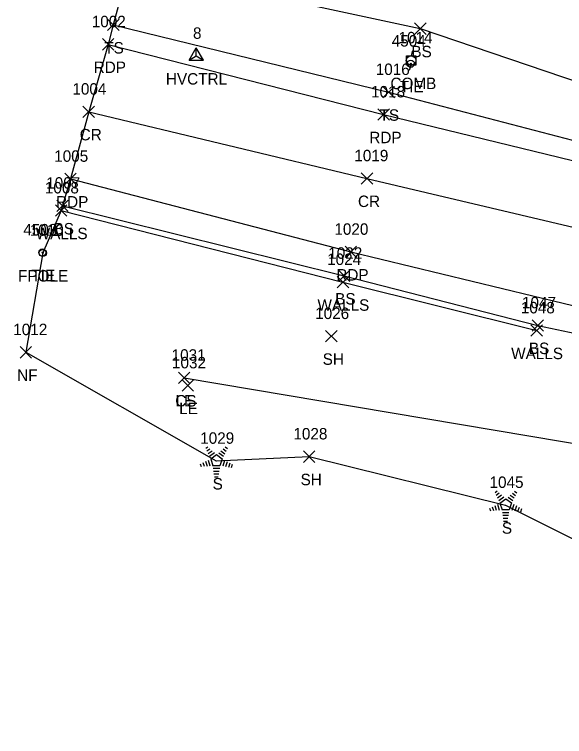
# Model space of a CAD drawing. Extents: x 1509053 to 1511576, y 400838 to 402572.
# Drawn here: x 1509053.4 to 1509149.6, y 402041.6 to 402167.8 of the extents above; entities that cross this region are included whole.
import ezdxf

# ---------------------------------------------------------------- set-up
doc = ezdxf.new("R2010")
doc.units = 0
for name, color, linetype in [('C_A', 7, 'Continuous'), ('C_I', 7, 'Continuous'), ('CBP', 7, 'Continuous'), ('CPSM', 7, 'Continuous'), ('L_A', 7, 'Continuous'), ('L_I', 7, 'Continuous'), ('L_TIC', 7, 'Continuous'), ('LELB', 7, 'Continuous'), ('LFP', 7, 'Continuous'), ('LSOGP', 7, 'Continuous'), ('LTC', 7, 'Continuous'), ('LWS', 7, 'Continuous'), ('P_A', 7, 'Continuous'), ('P_I', 7, 'Continuous'), ('P_TIC', 7, 'Continuous'), ('PET', 7, 'Continuous'), ('PRC', 7, 'Continuous'), ('U_A', 7, 'Continuous'), ('U_I', 7, 'Continuous'), ('UP', 7, 'Continuous')]:
    doc.layers.add(name, color=color, linetype=linetype)

msp = doc.modelspace()

# ---------------------------------------------------------------- linework, layer by layer
at = {"layer": 'CBP'}
for centre, radius in [((1509122.7, 402159.23), 0.625), ((1509122.7, 402159.23), 0.0833), ((1509058.25, 402126.22), 0.625), ((1509058.25, 402126.22), 0.0833)]:
    msp.add_circle(centre, radius, dxfattribs=at)
at = {"layer": 'CPSM'}
for p, q in [((1509083.92, 402159.86), (1509085.17, 402162.03)), ((1509086.42, 402159.86), (1509085.17, 402162.03)), ((1509085.17, 402160.58), (1509085.17, 402162.03)), ((1509083.92, 402159.86), (1509085.17, 402160.58)), ((1509083.92, 402159.86), (1509086.42, 402159.86)), ((1509085.17, 402160.58), (1509085.17, 402160.58)), ((1509085.17, 402160.58), (1509086.42, 402159.86))]:
    msp.add_line(p, q, dxfattribs=at)
at = {"layer": 'L_TIC'}
for points in [[(1509069.66, 402165.01), (1509071.66, 402167.01)], [(1509071.66, 402165.01), (1509069.66, 402167.01)], [(1509123.36, 402164.36), (1509125.36, 402166.36)], [(1509125.36, 402164.36), (1509123.36, 402166.36)], [(1509117.82, 402153.26), (1509119.82, 402155.26)], [(1509119.82, 402153.26), (1509117.82, 402155.26)], [(1509060.54, 402132.56), (1509062.54, 402134.56)], [(1509062.54, 402132.56), (1509060.54, 402134.56)], [(1509060.77, 402133.39), (1509062.77, 402135.39)], [(1509062.77, 402133.39), (1509060.77, 402135.39)], [(1509110.03, 402121.14), (1509112.03, 402123.14)], [(1509112.03, 402121.14), (1509110.03, 402123.14)], [(1509109.83, 402120.05), (1509111.83, 402122.05)], [(1509111.83, 402120.05), (1509109.83, 402122.05)], [(1509143.92, 402112.48), (1509145.92, 402114.48)], [(1509145.92, 402112.48), (1509143.92, 402114.48)], [(1509143.72, 402111.59), (1509145.72, 402113.59)], [(1509145.72, 402111.59), (1509143.72, 402113.59)], [(1509107.79, 402110.6), (1509109.79, 402112.6)], [(1509109.79, 402110.6), (1509107.79, 402112.6)], [(1509054.36, 402107.79), (1509056.36, 402109.79)], [(1509056.36, 402107.79), (1509054.36, 402109.79)], [(1509082.06, 402103.32), (1509084.06, 402105.32)], [(1509084.06, 402103.32), (1509082.06, 402105.32)], [(1509082.06, 402103.32), (1509084.06, 402105.32)], [(1509084.06, 402103.32), (1509082.06, 402105.32)], [(1509082.7, 402101.98), (1509084.7, 402103.98)], [(1509084.7, 402101.98), (1509082.7, 402103.98)], [(1509103.93, 402089.55), (1509105.93, 402091.55)], [(1509105.93, 402089.55), (1509103.93, 402091.55)]]:
    msp.add_lwpolyline(points, dxfattribs=at)
at = {"layer": 'LELB'}
for points in [[(1509073.43, 402176.32), (1509124.36, 402165.36), (1509168.15, 402150.53), (1509197.52, 402153.15), (1509206.41, 402183.98), (1509229.57, 402218.52), (1509244.53, 402232.65)], [(1509070.66, 402166.02), (1509118.82, 402154.26), (1509167.06, 402141.7), (1509189.96, 402136.47)], [(1509061.77, 402134.39), (1509111.03, 402122.14), (1509144.92, 402113.48)], [(1509144.92, 402113.48), (1509159.31, 402110.46)], [(1509083.06, 402104.32), (1509155.46, 402092.16)]]:
    msp.add_lwpolyline(points, dxfattribs=at)
at = {"layer": 'LFP'}
for radius in [0.625, 0.0833]:
    msp.add_circle((1509058.33, 402126.15), radius, dxfattribs=at)
at = {"layer": 'LSOGP'}
msp.add_lwpolyline([(1509099.68, 402257.85), (1509084.77, 402216.15), (1509076.57, 402183.15), (1509073.43, 402176.32), (1509070.66, 402166.02), (1509069.74, 402162.61), (1509066.35, 402150.83), (1509063.17, 402139.09), (1509061.77, 402134.39), (1509061.54, 402133.56), (1509058.33, 402126.15), (1509055.36, 402108.79), (1509088.64, 402089.81), (1509104.93, 402090.55), (1509139.24, 402082.08), (1509152.55, 402075.44), (1509177.52, 402071.59), (1509197.64, 402060.42), (1509219.32, 402052.84), (1509231.98, 402043.7), (1509281.69, 402042.53)], dxfattribs=at)
at = {"layer": 'LTC'}
for p, q in [((1509086.84, 402092.01), (1509087.19, 402092.27)), ((1509087.04, 402091.55), (1509087.57, 402091.93)), ((1509087.25, 402091.08), (1509087.96, 402091.59)), ((1509089.49, 402091.56), (1509090.17, 402091.06)), ((1509089.86, 402091.91), (1509090.41, 402091.51)), ((1509090.23, 402092.25), (1509090.65, 402091.95)), ((1509087.46, 402090.62), (1509088.34, 402091.25)), ((1509087.69, 402090.16), (1509088.7, 402090.9)), ((1509088.7, 402090.9), (1509089.7, 402090.17)), ((1509089.12, 402091.21), (1509089.93, 402090.62)), ((1509085.87, 402089.29), (1509086.02, 402088.82)), ((1509086.32, 402089.51), (1509086.53, 402088.86)), ((1509086.78, 402089.73), (1509087.05, 402088.89)), ((1509087.23, 402089.94), (1509087.56, 402088.92)), ((1509087.69, 402090.16), (1509088.08, 402088.97)), ((1509089.7, 402090.17), (1509089.31, 402088.97)), ((1509090.13, 402089.9), (1509089.8, 402088.86)), ((1509090.58, 402089.65), (1509090.29, 402088.76)), ((1509091.02, 402089.4), (1509090.79, 402088.67)), ((1509091.47, 402089.15), (1509091.28, 402088.57)), ((1509089.31, 402088.97), (1509088.08, 402088.97)), ((1509089.27, 402088.47), (1509088.12, 402088.47)), ((1509089.18, 402087.97), (1509088.2, 402087.97)), ((1509089.1, 402087.47), (1509088.27, 402087.47)), ((1509089.02, 402086.97), (1509088.34, 402086.97)), ((1509137.44, 402084.29), (1509137.79, 402084.55)), ((1509137.65, 402083.82), (1509138.18, 402084.21)), ((1509140.47, 402084.18), (1509141.01, 402083.78)), ((1509140.84, 402084.53), (1509141.26, 402084.23)), ((1509137.86, 402083.36), (1509138.56, 402083.87)), ((1509138.07, 402082.89), (1509138.95, 402083.53)), ((1509138.29, 402082.44), (1509139.3, 402083.17)), ((1509139.3, 402083.17), (1509140.3, 402082.45)), ((1509139.72, 402083.49), (1509140.53, 402082.9)), ((1509140.09, 402083.83), (1509140.77, 402083.34)), ((1509136.47, 402081.57), (1509136.62, 402081.1)), ((1509136.93, 402081.79), (1509137.14, 402081.13)), ((1509137.38, 402082), (1509137.65, 402081.17)), ((1509137.84, 402082.22), (1509138.17, 402081.2)), ((1509138.29, 402082.44), (1509138.68, 402081.24)), ((1509140.3, 402082.45), (1509139.91, 402081.24)), ((1509140.74, 402082.18), (1509140.4, 402081.14)), ((1509141.18, 402081.93), (1509140.89, 402081.04)), ((1509141.63, 402081.68), (1509141.39, 402080.95)), ((1509142.07, 402081.43), (1509141.88, 402080.85)), ((1509139.91, 402081.24), (1509138.68, 402081.24)), ((1509139.87, 402080.74), (1509138.73, 402080.74)), ((1509139.79, 402080.24), (1509138.8, 402080.24)), ((1509139.7, 402079.74), (1509138.87, 402079.74)), ((1509139.62, 402079.24), (1509138.94, 402079.24))]:
    msp.add_line(p, q, dxfattribs=at)
at = {"layer": 'LWS'}
msp.add_lwpolyline([(1509061.54, 402133.56), (1509110.83, 402121.05), (1509144.72, 402112.59)], dxfattribs=at)
at = {"layer": 'P_TIC'}
for points in [[(1509068.74, 402161.61), (1509070.74, 402163.61)], [(1509070.74, 402161.61), (1509068.74, 402163.61)], [(1509065.35, 402149.83), (1509067.35, 402151.83)], [(1509067.35, 402149.83), (1509065.35, 402151.83)], [(1509116.95, 402149.34), (1509118.95, 402151.34)], [(1509118.95, 402149.34), (1509116.95, 402151.34)], [(1509062.17, 402138.09), (1509064.17, 402140.09)], [(1509064.17, 402138.09), (1509062.17, 402140.09)], [(1509114.03, 402138.18), (1509116.03, 402140.18)], [(1509116.03, 402138.18), (1509114.03, 402140.18)], [(1509111.19, 402125.33), (1509113.19, 402127.33)], [(1509113.19, 402125.33), (1509111.19, 402127.33)]]:
    msp.add_lwpolyline(points, dxfattribs=at)
at = {"layer": 'PET'}
for points in [[(1509069.74, 402162.61), (1509117.95, 402150.34), (1509166.31, 402138.6), (1509189.12, 402132.7), (1509214.97, 402125.92), (1509263.51, 402114.05), (1509312.14, 402102.42), (1509361.01, 402091.29), (1509409.6, 402078.35), (1509458.22, 402062.29), (1509505.25, 402041.71), (1509550.77, 402018.3), (1509593.93, 401993.28)], [(1509063.17, 402139.09), (1509112.19, 402126.33), (1509159.98, 402114.82), (1509209.05, 402103), (1509244.49, 402094.13), (1509308.65, 402080.15), (1509355.93, 402069.3), (1509402.46, 402055.88), (1509449.73, 402039.91), (1509495.54, 402020.72), (1509539.16, 401999.24), (1509581.25, 401974.02)]]:
    msp.add_lwpolyline(points, dxfattribs=at)
at = {"layer": 'PRC'}
msp.add_lwpolyline([(1509066.35, 402150.83), (1509115.03, 402139.18), (1509163.71, 402127.66), (1509212.43, 402116.11), (1509261.18, 402104.85), (1509309.89, 402093.3), (1509358.23, 402080.96), (1509406.48, 402067.02), (1509453.83, 402051.04), (1509500, 402031.81), (1509544.56, 402009.22), (1509587.94, 401984.24)], dxfattribs=at)
at = {"layer": 'UP'}
for p, q in [((1509123, 402161.46), (1509122.75, 402160.63)), ((1509121.92, 402158.96), (1509121.92, 402160.63)), ((1509121.92, 402160.63), (1509123.59, 402160.63)), ((1509122.75, 402159.79), (1509122.75, 402159.79)), ((1509123.59, 402160.63), (1509123.59, 402158.96)), ((1509123.59, 402158.96), (1509121.92, 402158.96)), ((1509122.5, 402158.13), (1509122.75, 402158.96))]:
    msp.add_line(p, q, dxfattribs=at)
msp.add_circle((1509122.75, 402159.79), 0.833, dxfattribs=at)

# ---------------------------------------------------------------- texts
at = {"layer": 'C_A'}
for s, p in [('HVCTRL', (1509079.86, 402155.58)), ('TIE', (1509120.78, 402154.23)), ('TIE', (1509056.33, 402121.22))]:
    msp.add_text(s, height=2, dxfattribs=at).set_placement(p)
at = {"layer": 'C_I'}
for s, p in [('8', (1509084.6, 402163.58)), ('4504', (1509119.36, 402162.23)), ('4503', (1509054.91, 402129.22))]:
    msp.add_text(s, height=2, dxfattribs=at).set_placement(p)
at = {"layer": 'L_A'}
for s, p in [('TS', (1509069.07, 402161.01)), ('BS', (1509122.8, 402160.36)), ('TS', (1509117.23, 402149.26)), ('BS', (1509060.21, 402129.39)), ('WALLS', (1509057.09, 402128.56)), ('FPOLE', (1509054, 402121.15)), ('WALLS', (1509106.37, 402116.05)), ('BS', (1509109.47, 402117.14)), ('BS', (1509143.36, 402108.48)), ('WALLS', (1509140.26, 402107.59)), ('SH', (1509107.28, 402106.6)), ('NF', (1509053.84, 402103.79)), ('CS', (1509081.5, 402099.32)), ('LE', (1509081.55, 402099.32)), ('LE', (1509082.18, 402097.98)), ('S', (1509088.03, 402084.8)), ('SH', (1509103.42, 402085.55)), ('S', (1509138.63, 402077.08))]:
    msp.add_text(s, height=2, dxfattribs=at).set_placement(p)
at = {"layer": 'L_I'}
for s, p in [('1016', (1509116.56, 402157.26)), ('1008', (1509058.69, 402136.56)), ('1007', (1509058.92, 402137.39)), ('1010', (1509056.04, 402129.15)), ('1022', (1509108.26, 402125.14)), ('1024', (1509108.06, 402124.05)), ('1047', (1509142.15, 402116.48)), ('1048', (1509141.95, 402115.59)), ('1026', (1509105.97, 402114.6)), ('1012', (1509053.16, 402111.79)), ('1031', (1509080.86, 402107.32)), ('1031', (1509080.86, 402107.32)), ('1032', (1509080.92, 402105.98)), ('1028', (1509102.16, 402093.55)), ('1029', (1509085.86, 402092.8)), ('1045', (1509136.47, 402085.08))]:
    msp.add_text(s, height=2, dxfattribs=at).set_placement(p)
at = {"layer": 'LTC'}
for p in [(1509088.58, 402089.91), (1509139.19, 402082.19)]:
    msp.add_text('.', height=1.04, rotation=270, dxfattribs=at).set_placement(p)
at = {"layer": 'P_A'}
for s, p in [('RDP', (1509067.23, 402157.61)), ('CR', (1509064.78, 402145.83)), ('RDP', (1509115.44, 402145.34)), ('RDP', (1509060.65, 402134.09)), ('CR', (1509113.46, 402134.18)), ('RDP', (1509109.67, 402121.33))]:
    msp.add_text(s, height=2, dxfattribs=at).set_placement(p)
at = {"layer": 'P_I'}
for s, p in [('1002', (1509066.89, 402165.61)), ('1004', (1509063.5, 402153.83)), ('1018', (1509115.74, 402153.34)), ('1005', (1509060.32, 402142.09)), ('1019', (1509112.82, 402142.18)), ('1020', (1509109.33, 402129.33))]:
    msp.add_text(s, height=2, dxfattribs=at).set_placement(p)
at = {"layer": 'U_A'}
msp.add_text('COMB', height=2, dxfattribs=at).set_placement((1509119.14, 402154.79))
at = {"layer": 'U_I'}
msp.add_text('1014', height=2, dxfattribs=at).set_placement((1509120.55, 402162.79))

doc.saveas('drawing.dxf')
